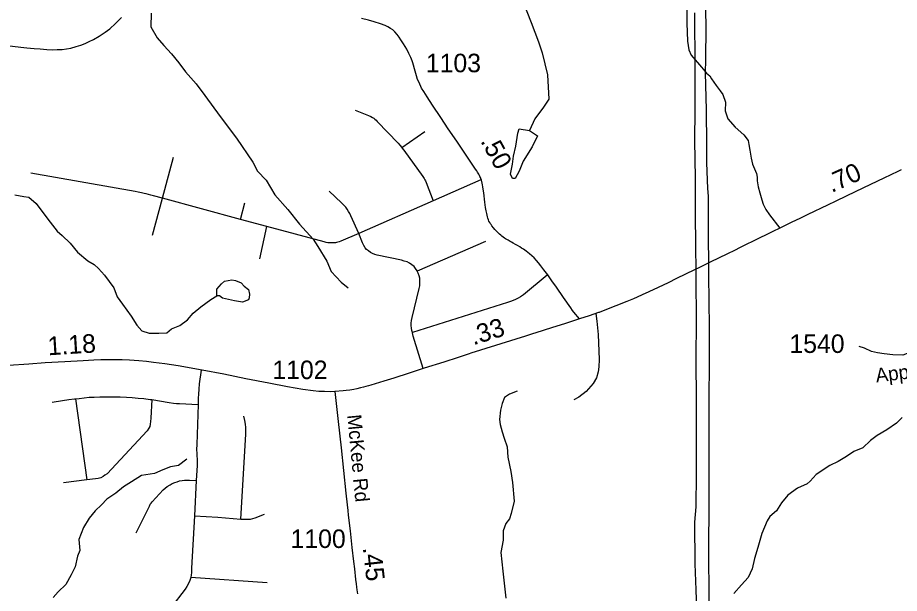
# Model space of a CAD drawing. Extents: x 1383679 to 1536984, y 460658 to 651027.
# Drawn here: x 1393020 to 1398965, y 486110 to 489995 of the extents above; entities that cross this region are included whole.
import ezdxf

# ---------------------------------------------------------------- set-up
doc = ezdxf.new("R2010")
doc.units = 0
for name, color, linetype in [('Exist Hydrographic Misc Water Feature', 7, 'Continuous'), ('Exist Road Non-System Type 51', 7, 'Continuous'), ('Exist Road Secondary Mileage Hundredths English Label', 7, 'Continuous'), ('Exist Road Secondary Type 51 Attributed', 7, 'Continuous'), ('Exist Road Secondary Type 51 Label', 7, 'Continuous'), ('Exist Road Secondary Type 51 Number Label', 7, 'Continuous'), ('Exist Utilities Electrical Transmission Line', 7, 'Continuous')]:
    doc.layers.add(name, color=color, linetype=linetype)

msp = doc.modelspace()

# ---------------------------------------------------------------- linework, layer by layer
at = {"layer": 'Exist Hydrographic Misc Water Feature'}
for points in [[(1396428, 490100.1), (1396481.1, 489962.8), (1396532.3, 489832.1), (1396556.8, 489757.7), (1396591.8, 489608.5), (1396602.3, 489444.2), (1396565.2, 489390.8), (1396507.5, 489312.4), (1396471.8, 489232.6)], [(1393919.1, 490024.1), (1393917.3, 489932.3), (1393959.7, 489857.5), (1394004.7, 489806.6), (1394057.6, 489751.4), (1394106.4, 489690.5), (1394151.1, 489628.9), (1394223.3, 489547.8), (1394281.8, 489470.3), (1394384.9, 489327.9), (1394496, 489182.1), (1394604.5, 489019.1), (1394637.3, 488958.5), (1394696.2, 488897.4), (1394754.1, 488800.2), (1394842.1, 488700), (1394920.1, 488602.4), (1395012, 488500.4), (1395042.9, 488449.8), (1395105, 488352.5), (1395133.6, 488282.2), (1395202.1, 488211.1), (1395247.3, 488171.6)], [(1396471.8, 489232.6), (1396525.3, 489197.9), (1396489.7, 489122.3), (1396427.7, 489027.5), (1396400.2, 488958.3), (1396375.1, 488908.8), (1396355.1, 488909.2), (1396341.7, 488939.8), (1396357.1, 489005.2), (1396362.2, 489059.2), (1396379.7, 489128.6), (1396391.5, 489214.5), (1396400.1, 489244.7), (1396471.8, 489232.6)], [(1393001.3, 488800.2), (1393061.1, 488789.1), (1393094.9, 488782.7), (1393144.2, 488741.5), (1393222.1, 488635.7), (1393286.4, 488554.8), (1393319.7, 488523.8), (1393374.6, 488472.7), (1393423.4, 488411.8), (1393492.3, 488354.6), (1393535.8, 488329.1), (1393565.2, 488302.2), (1393604.3, 488258), (1393668.6, 488172.2), (1393691.3, 488111.8), (1393726.3, 488061), (1393784.6, 487980.2), (1393823.4, 487918.8), (1393856.7, 487882.8), (1393906.3, 487867), (1393972.4, 487865.7), (1394026.5, 487868.7), (1394057, 487894.4), (1394113.4, 487917), (1394164.3, 487956.2), (1394203.2, 488001.4), (1394254.2, 488043.8), (1394321.3, 488092.5), (1394361.8, 488118)], [(1394361.8, 488118), (1394362.7, 488162.3), (1394393.4, 488197.8), (1394413.8, 488217.1), (1394464.1, 488225.9), (1394488, 488221.3), (1394527.6, 488204.9), (1394547.2, 488184), (1394576.8, 488159.7), (1394582.1, 488129.2), (1394581.6, 488103.7), (1394575.2, 488089.9), (1394534.9, 488074.3), (1394481.1, 488085.2), (1394401.4, 488101.6), (1394381.7, 488117.6), (1394361.8, 488118)], [(1396387.3, 487474.1), (1396336.9, 487454.6), (1396302.5, 487431.5), (1396285.6, 487391.7), (1396274.7, 487345.9), (1396269.4, 487284.5), (1396272.6, 487249.9), (1396287.6, 487199.6), (1396300.7, 487157.5), (1396319.5, 487098.9), (1396324.1, 487029), (1396346, 486932.6), (1396356.5, 486858.5), (1396368, 486733.5), (1396346.1, 486648.6), (1396335.4, 486612.7), (1396310.8, 486582.9), (1396293.8, 486533.1), (1396292.3, 486469.2), (1396276.6, 486385.8), (1396290.1, 486259.1), (1396310.4, 486079)], [(1398982.9, 487298), (1398946, 487258.6), (1398881.1, 487214), (1398814.3, 487175), (1398769.6, 487142.3), (1398718.5, 487093.3), (1398657.9, 487068.3), (1398607.2, 487033.1), (1398552.5, 487000.6), (1398495.9, 486972.2), (1398404.7, 486913.3), (1398363.7, 486868.2), (1398343.2, 486848.9), (1398278.6, 486820.7), (1398213.6, 486771.9), (1398170.5, 486720.2), (1398135.3, 486666.8), (1398090.6, 486630), (1398073.9, 486600.7), (1398038.1, 486515.3), (1398010.1, 486419.9), (1397988.7, 486345.6), (1397973.2, 486276.2), (1397946, 486216.8), (1397900.9, 486167.7), (1397849.6, 486108.8)], [(1394160.8, 487015.9), (1394103.9, 486972.7), (1394049.7, 486963.9), (1393999.1, 486942.8), (1393942.7, 486920.1), (1393854.4, 486906.3), (1393787.4, 486863.4), (1393732.7, 486828.4), (1393681.8, 486785.9), (1393620.9, 486746.9), (1393584.1, 486707.4), (1393543.3, 486668.1), (1393502.3, 486618.8), (1393462.9, 486553.9), (1393431.2, 486474.2), (1393439.6, 486400.2), (1393422.8, 486360.3), (1393407.2, 486289.2), (1393380.3, 486235.5), (1393344.9, 486169.8), (1393293.8, 486120.8), (1393259, 486082.1)]]:
    msp.add_lwpolyline(points, dxfattribs=at)
at = {"layer": 'Exist Road Non-System Type 51'}
for p, q in [((1395766, 489224.2), (1395611.1, 489117.1)), ((1393995.9, 488775.8), (1394070.1, 489053.6)), ((1396143.1, 488899.5), (1395821, 488758.6)), ((1393929.6, 488527.6), (1393995.9, 488775.8)), ((1394522.9, 488633.6), (1393995.9, 488775.8)), ((1395821, 488758.6), (1395319, 488539.1)), ((1394522.9, 488633.6), (1394551.4, 488746)), ((1394700.6, 488585.6), (1394522.9, 488633.6)), ((1394652.1, 488368.5), (1394700.6, 488585.6)), ((1396173.5, 488484.6), (1395713.6, 488284.8)), ((1393410.2, 487423.2), (1393486.4, 486875.3)), ((1393486.4, 486875.3), (1393329.9, 486857.2)), ((1394224.1, 486871.5), (1394211.5, 486634.6)), ((1394187.4, 486220.2), (1394703, 486184.7))]:
    msp.add_line(p, q, dxfattribs=at)
for points in [[(1397532.1, 490049.5), (1397532.1, 489957.7), (1397536.4, 489836.9), (1397545.4, 489777.3), (1397561.1, 489742.6), (1397629.9, 489659.8), (1397664.5, 489621), (1397686.1, 489601.1), (1397697.6, 489582.1), (1397729.1, 489536.6), (1397756.4, 489501.8), (1397773.8, 489475.3), (1397792.8, 489424.9), (1397791.1, 489366.2), (1397807.6, 489311.6), (1397857.4, 489256.2), (1397915.1, 489204.8), (1397945, 489165.2), (1397950.8, 489138.7), (1397955.8, 489099.8), (1397964.9, 489046.8), (1397974.8, 489005.5), (1397988, 488974), (1398002.1, 488944.2), (1398006.2, 488917.8), (1398005.4, 488892.9), (1398013.6, 488852.4), (1398024.4, 488811.8), (1398037.6, 488764.8), (1398046.8, 488735.8), (1398064.1, 488701), (1398088.1, 488665.4), (1398158.2, 488574)], [(1392888.5, 489813.8), (1393041.4, 489796.3), (1393081.6, 489792.1), (1393131.8, 489787.3), (1393172.4, 489784.1), (1393216.2, 489780.8), (1393253.4, 489778.2), (1393286.6, 489778.8), (1393319.2, 489779.7), (1393348.2, 489784.4), (1393377.6, 489789.2), (1393413.9, 489799.4), (1393444.6, 489809.3), (1393474, 489821.3), (1393502.2, 489833.8), (1393530.9, 489847.8), (1393568.4, 489868.9), (1393610.1, 489896.2), (1393640.4, 489919), (1393679.8, 489955.2), (1393718.8, 489995)], [(1395296.4, 489370.7), (1395386.2, 489333.8), (1395401.6, 489327.2), (1395412.4, 489321.4), (1395420.6, 489315.6), (1395428.1, 489309.8), (1395435.9, 489303.2), (1395444.2, 489294.9), (1395584.6, 489147.8), (1395597.4, 489134.2), (1395609.5, 489119.2), (1395611.1, 489117.1)], [(1395611.1, 489117.1), (1395623.1, 489101.1), (1395751.1, 488922.2), (1395760.6, 488908.9), (1395765.1, 488901.4), (1395769.4, 488893.2), (1395773.5, 488883.2), (1395821, 488758.6)], [(1393995.9, 488775.8), (1393936, 488791.9), (1393916.6, 488797.3), (1393901.1, 488801.5), (1393886.8, 488805.2), (1393873.1, 488808.7), (1393855.4, 488812.6), (1393831.2, 488817.2), (1393810.9, 488820.7), (1393108.1, 488946.5)], [(1395319, 488539.1), (1395266.9, 488658.3), (1395259.4, 488673.3), (1395251.1, 488687.9), (1395242.4, 488701.7), (1395231.5, 488715.8), (1395219, 488729.2), (1395203.6, 488744.6), (1395120.8, 488824.1)], [(1395319, 488539.1), (1395198.1, 488486.2), (1395188.1, 488482), (1395179.4, 488479.2), (1395170.1, 488477), (1395162, 488475.8), (1395152.8, 488474.8), (1395142.1, 488474.4), (1395132, 488474.4), (1395120.4, 488475.2), (1395110.5, 488476.4), (1395099.5, 488478.4), (1395085.8, 488481.6), (1394700.6, 488585.6)], [(1395713.6, 488284.8), (1395713.1, 488285.6), (1395702.9, 488302.3), (1395692.1, 488315), (1395678.1, 488327.4), (1395662.6, 488338.2), (1395645.1, 488346.9), (1395626, 488352.8), (1395607.2, 488357.7), (1395443.4, 488392.3), (1395428.2, 488396.4), (1395411.4, 488403.8), (1395398.5, 488411.1), (1395385.2, 488420.8), (1395372.9, 488431.2), (1395363.2, 488442.2), (1395354.6, 488456.4), (1395345.9, 488475.7), (1395319, 488539.1)], [(1395680.9, 487870.7), (1395677.6, 487884.2), (1395674.9, 487900.7), (1395673.1, 487917.2), (1395673.1, 487932.5), (1395674.9, 487950.7), (1395678.9, 487971.8), (1395726.4, 488166.2), (1395730.4, 488185.7), (1395732.2, 488202.8), (1395732.2, 488219.9), (1395730.6, 488236.2), (1395727.1, 488252.5), (1395721.1, 488270.1), (1395713.6, 488284.8)], [(1396590.9, 488256.6), (1396430, 488125.2), (1396409.4, 488110.4), (1396394.1, 488101), (1396376.1, 488092), (1396360.4, 488085.7), (1396343.4, 488079.3), (1396323.4, 488073), (1395680.9, 487870.7)], [(1396919, 487998.7), (1396925.6, 487946.2), (1396934.1, 487856.9), (1396940.1, 487689.2), (1396939, 487638.5), (1396934.1, 487604.7), (1396922.1, 487563.7), (1396899.1, 487527.4), (1396853.2, 487473.1), (1396803.8, 487434.5), (1396770, 487416.4)], [(1395754.6, 487627.3), (1395687.4, 487846.6), (1395681.6, 487867.1), (1395680.9, 487870.7)], [(1394256.6, 487616.6), (1394244.4, 487523.3), (1394240.9, 487487.5), (1394239.1, 487455.2), (1394237.4, 487426.3), (1394235.9, 487383.6)], [(1393251.4, 487400.3), (1393322, 487412.2), (1393364.8, 487418.2), (1393402.5, 487422.2), (1393410.2, 487423.2)], [(1393410.2, 487423.2), (1393435.4, 487426.2), (1393469.1, 487430.2), (1393501, 487433.2), (1393534.9, 487435.2), (1393574.6, 487436.2), (1393624.4, 487437.2), (1393668.1, 487437.2), (1393709.9, 487436.2), (1393752.6, 487435.2), (1393792.5, 487432.2), (1393831.2, 487428.2), (1393871.1, 487424.2), (1393913.9, 487419.2), (1393923.4, 487417.6)], [(1393923.4, 487417.6), (1393917.9, 487292.9), (1393915.9, 487270), (1393912.9, 487251.2), (1393909.9, 487237.2), (1393903.9, 487225.2), (1393891.9, 487206.3), (1393622.4, 486917.9), (1393608.4, 486906.9), (1393595.5, 486898), (1393579.6, 486891), (1393562.6, 486885.1), (1393544.8, 486882.1), (1393486.4, 486875.3)], [(1393923.4, 487417.6), (1394042.1, 487397.3), (1394070, 487393.4), (1394090.9, 487391.4), (1394111.9, 487390.4), (1394235.9, 487383.6)], [(1394235.9, 487383.6), (1394226.9, 487115.2), (1394226, 487082), (1394227.8, 487054.9), (1394229.5, 486999), (1394229.5, 486973.6), (1394224.1, 486871.5)], [(1394525.1, 486611), (1394557.8, 487183.9), (1394558.6, 487209.2), (1394558.6, 487229.9), (1394556.9, 487252.4), (1394552.4, 487276.8), (1394544.1, 487305.7)], [(1393819.2, 486518.9), (1393908.6, 486698.8), (1393913.9, 486711.7), (1393920, 486719.7), (1393926.6, 486727.8), (1393999.9, 486809), (1394014, 486820.4), (1394028.1, 486831.2), (1394046.9, 486843.2), (1394062.4, 486851.9), (1394079.8, 486859.3), (1394094.5, 486864), (1394111.4, 486868.8), (1394128.1, 486871.4), (1394144.9, 486873.4), (1394161.6, 486874.1), (1394178.4, 486874.1), (1394224.1, 486871.5)], [(1394211.5, 486634.6), (1394192.8, 486279.8), (1394191.9, 486251.8), (1394190.1, 486234.3), (1394187.4, 486220.2)], [(1394211.5, 486634.6), (1394370.5, 486623.7), (1394525.1, 486611)], [(1394525.1, 486611), (1394553.2, 486611), (1394589.2, 486611), (1394620.5, 486620.3), (1394683, 486645.3)], [(1394187.4, 486220.2), (1394186.6, 486216.8), (1394181.4, 486197.6), (1394171.8, 486177.5), (1394161.4, 486157.4), (1394149.1, 486138.2), (1393955.9, 485885.8)]]:
    msp.add_lwpolyline(points, dxfattribs=at)
at = {"layer": 'Exist Road Secondary Type 51 Attributed'}
for points in [[(1396807.1, 487962.7), (1396770, 488008), (1396761.3, 488019.5), (1396748.6, 488037.4), (1396699.8, 488107.5), (1396652.9, 488176), (1396622, 488219.7), (1396594.4, 488258.6), (1396568.2, 488293), (1396548.1, 488319.4), (1396532.1, 488340.1), (1396518.6, 488355.9), (1396501.4, 488373.6), (1396486.6, 488387.9), (1396470.6, 488401.8), (1396448.5, 488418.9), (1396439.2, 488425.9), (1396430.8, 488431.9), (1396417.9, 488440.5), (1396405.3, 488448.4), (1396390.5, 488456.9), (1396376.9, 488464.7), (1396360.7, 488473.6), (1396348.4, 488480.5), (1396339.4, 488485.5), (1396327, 488492.4), (1396318.5, 488497.4), (1396310.1, 488502.7), (1396301.6, 488507.9), (1396293.8, 488513.3), (1396285, 488519.8), (1396276.5, 488526.8), (1396269.3, 488533.4), (1396258.8, 488543.1), (1396246, 488556.1), (1396237.1, 488566.1), (1396227.8, 488576.5), (1396217, 488590.4), (1396211.3, 488598.5), (1396205.9, 488606.6), (1396202.4, 488612.8), (1396197.7, 488622.4), (1396194.3, 488631.3), (1396190.8, 488641.3), (1396187.7, 488651), (1396185, 488662.1), (1396182.3, 488673.7), (1396180.4, 488682.6), (1396178.8, 488691.5), (1396176.9, 488702.3), (1396175, 488713.4), (1396170, 488750.6), (1396163.2, 488811.7), (1396159.5, 488836.5), (1396156.8, 488853.1), (1396154.5, 488866.9), (1396152.2, 488878.1), (1396149.5, 488889.3), (1396146.4, 488899.3), (1396143, 488909), (1396139.5, 488917.1), (1396136.4, 488923.3), (1396133.3, 488929.4), (1396128.3, 488938.3), (1396123.7, 488946), (1396120.2, 488951.8), (1396114.8, 488960.3), (1396107.1, 488972.2), (1396093.6, 488992.7), (1396075, 489020), (1396044.4, 489066), (1395980.1, 489161), (1395923.1, 489243.9), (1395873.3, 489320.4), (1395817.9, 489404), (1395781.5, 489459.4), (1395758.1, 489495.9), (1395743.5, 489519.7), (1395726.1, 489556.9), (1395716.4, 489576.9), (1395708.1, 489602.9), (1395700.3, 489632.5), (1395683.8, 489689), (1395679.3, 489703.4), (1395670.5, 489725.9), (1395657.8, 489752.4), (1395643.2, 489781.4), (1395621.1, 489817.4), (1395604.3, 489844.9), (1395592.5, 489863.4), (1395579.6, 489880.8), (1395562.6, 489898.2), (1395548.4, 489911.5), (1395533.6, 489922.3), (1395515.1, 489933.4), (1395498.2, 489941), (1395467.2, 489952.6), (1395423.8, 489966.1), (1395384.9, 489976.8), (1395337.2, 489988.6)], [(1398977.3, 488968.7), (1398954.6, 488957.6), (1398859.3, 488911.8), (1398722.5, 488846.4), (1398606.4, 488791), (1398535.4, 488757), (1398479.5, 488730.4), (1398346.9, 488665.7), (1398292.7, 488639.8), (1398240.3, 488614.7), (1398159.3, 488574.5), (1398112.1, 488551.1), (1397978.3, 488486.7), (1397931.9, 488463.1), (1397892.2, 488443.5), (1397852.9, 488424), (1397806.5, 488401.8), (1397745.6, 488371.9), (1397693.1, 488346.5), (1397640, 488321.3), (1397612.1, 488307.6), (1397583, 488293.2), (1397461.3, 488233.7), (1397404.9, 488205.8), (1397338.7, 488173.9), (1397276.4, 488145.3), (1397231.6, 488124.8), (1397197.6, 488109.8), (1397172.6, 488098.6), (1397126.3, 488079), (1396979.9, 488020.8), (1396939.5, 488005.6), (1396936.6, 488004.6), (1396873.1, 487983.2), (1396807.1, 487962.7)], [(1396807.1, 487962.7), (1396732.8, 487937.8), (1396713.3, 487931.6), (1396619.5, 487901.8), (1396513.1, 487867.7), (1396490.4, 487860.5), (1396443, 487845.4), (1396074.5, 487729.9), (1396064.5, 487726.6), (1395990.2, 487702.3), (1395892.4, 487671.2), (1395761.4, 487629.6), (1395659.8, 487596.3), (1395556.6, 487563.2), (1395488.1, 487541.9), (1395401.9, 487515.5), (1395385.1, 487510.1), (1395367.9, 487505.5), (1395350.7, 487500.9), (1395332.3, 487496.7), (1395307.4, 487491), (1395285.6, 487486.8), (1395259.5, 487482.2), (1395235.6, 487478.8), (1395214, 487476.5), (1395159.1, 487472)], [(1399513, 487891), (1399455.4, 487904.4), (1399403, 487904.4), (1399359.7, 487893), (1399325.6, 487881.6), (1399285.3, 487859.5), (1399236.8, 487838.3), (1399154.8, 487790.5), (1399075.5, 487752.2), (1398988.6, 487717.6), (1398920.3, 487719.9), (1398861.8, 487726.3), (1398817.8, 487733.5), (1398776.8, 487742.7), (1398729, 487765.4), (1398692.6, 487776.8)], [(1395159.1, 487472), (1395131.9, 487470.9), (1395087.5, 487472.2), (1395051.2, 487473.2), (1395012.6, 487476.6), (1394942, 487486.9), (1394839.1, 487504.8), (1394713.4, 487528.4), (1394558.1, 487558.8), (1394410.1, 487588.4), (1394263.1, 487615.7), (1394102.1, 487644.9), (1394011.9, 487659.3), (1393936.2, 487669.1), (1393888.5, 487673.9), (1393836.4, 487679.3), (1393774.6, 487684.5), (1393724.6, 487686.4), (1393694.4, 487686.7), (1393632.7, 487686.3), (1393581.3, 487685.4), (1393532.9, 487683.8), (1393460.4, 487680.3), (1393337.6, 487672.6), (1393204.6, 487664.8), (1393094.3, 487657.5), (1392957.3, 487647.3)], [(1395159.1, 487472), (1395181.3, 487270.9), (1395200.4, 487092.5), (1395232.4, 486785.8), (1395240.6, 486708.5), (1395245.2, 486669.6), (1395248.7, 486637.6), (1395261.2, 486532.3), (1395273.3, 486420.1), (1395284.5, 486326.5), (1395290.2, 486276.5), (1395298.4, 486203.8), (1395301.9, 486174.1), (1395304.6, 486153.3), (1395307.3, 486134), (1395311.2, 486107.7)]]:
    msp.add_lwpolyline(points, dxfattribs=at)
at = {"layer": 'Exist Utilities Electrical Transmission Line'}
for points in [[(1397655.3, 490160.6), (1397660.7, 489930.3), (1397658.1, 489712.3), (1397656.3, 489622.3), (1397663, 489372.1), (1397664.1, 489135.9), (1397663.7, 489015.9), (1397672, 488841.6), (1397674.9, 488789.6), (1397676.4, 488573.4), (1397678.1, 488275.3), (1397679.9, 488063.1), (1397682.9, 487925), (1397683.2, 487654.9), (1397680.7, 487428.8), (1397679.5, 487180.8), (1397679.8, 486906.6)], [(1397599, 486005.9), (1397593.8, 486134), (1397587.3, 486310.2), (1397585.2, 486590.4), (1397595.2, 486694.2), (1397595.9, 486914.3), (1397595.8, 487198.4), (1397596.7, 487430.5), (1397593.7, 487670.7), (1397595.8, 487970.8), (1397595, 488218.9), (1397595, 488311), (1397593.4, 488429), (1397591.1, 488701.2), (1397589.5, 488911.3), (1397586.6, 489165.5), (1397587, 489369.6), (1397587, 489657.7), (1397584.6, 490027.9)], [(1397679.8, 486906.6), (1397679.4, 486690.5), (1397678, 486430.5), (1397678.7, 486376.2), (1397679.1, 486098.1), (1397680.6, 485888), (1397684.4, 485775.8), (1397684.4, 485589.8), (1397686.7, 485503.7), (1397688.7, 485313.6), (1397685.5, 485067.5), (1397689.2, 484853.3), (1397687.5, 484681.3), (1397685.5, 484481.2), (1397684.7, 484251.2), (1397685.5, 484003), (1397684.8, 483869), (1397686.4, 483660.9), (1397686.2, 483462.8), (1397688.1, 483255.8)]]:
    msp.add_lwpolyline(points, dxfattribs=at)

# ---------------------------------------------------------------- texts
at = {"layer": 'Exist Road Secondary Mileage Hundredths English Label'}
for s, rotation, p in [('.50', 298.82045, (1396137.6, 489162.1)), ('.70', 24.19688, (1398508.1, 488811.5)), ('.33', 17.40119, (1396092.4, 487783.6)), ('1.18', 3.57657, (1393225.7, 487716.3)), ('.45', 276.38726, (1395346.6, 486417.8))]:
    msp.add_text(s, height=125, rotation=rotation, dxfattribs=at).set_placement(p)
at = {"layer": 'Exist Road Secondary Type 51 Label'}
for s, rotation, p in [('Appling Ln', 6.88856, (1398809.7, 487533.1)), ('McKee Rd', 275.3939, (1395241.6, 487313.3))]:
    msp.add_text(s, height=95, rotation=rotation, dxfattribs=at).set_placement(p)
at = {"layer": 'Exist Road Secondary Type 51 Number Label'}
for s, p in [('1103', (1395771.9, 489626.3)), ('1540', (1398223.3, 487732.6)), ('1102', (1394737.1, 487556.1)), ('1100', (1394859.7, 486416.6))]:
    msp.add_text(s, height=125, dxfattribs=at).set_placement(p)

doc.saveas('drawing.dxf')
